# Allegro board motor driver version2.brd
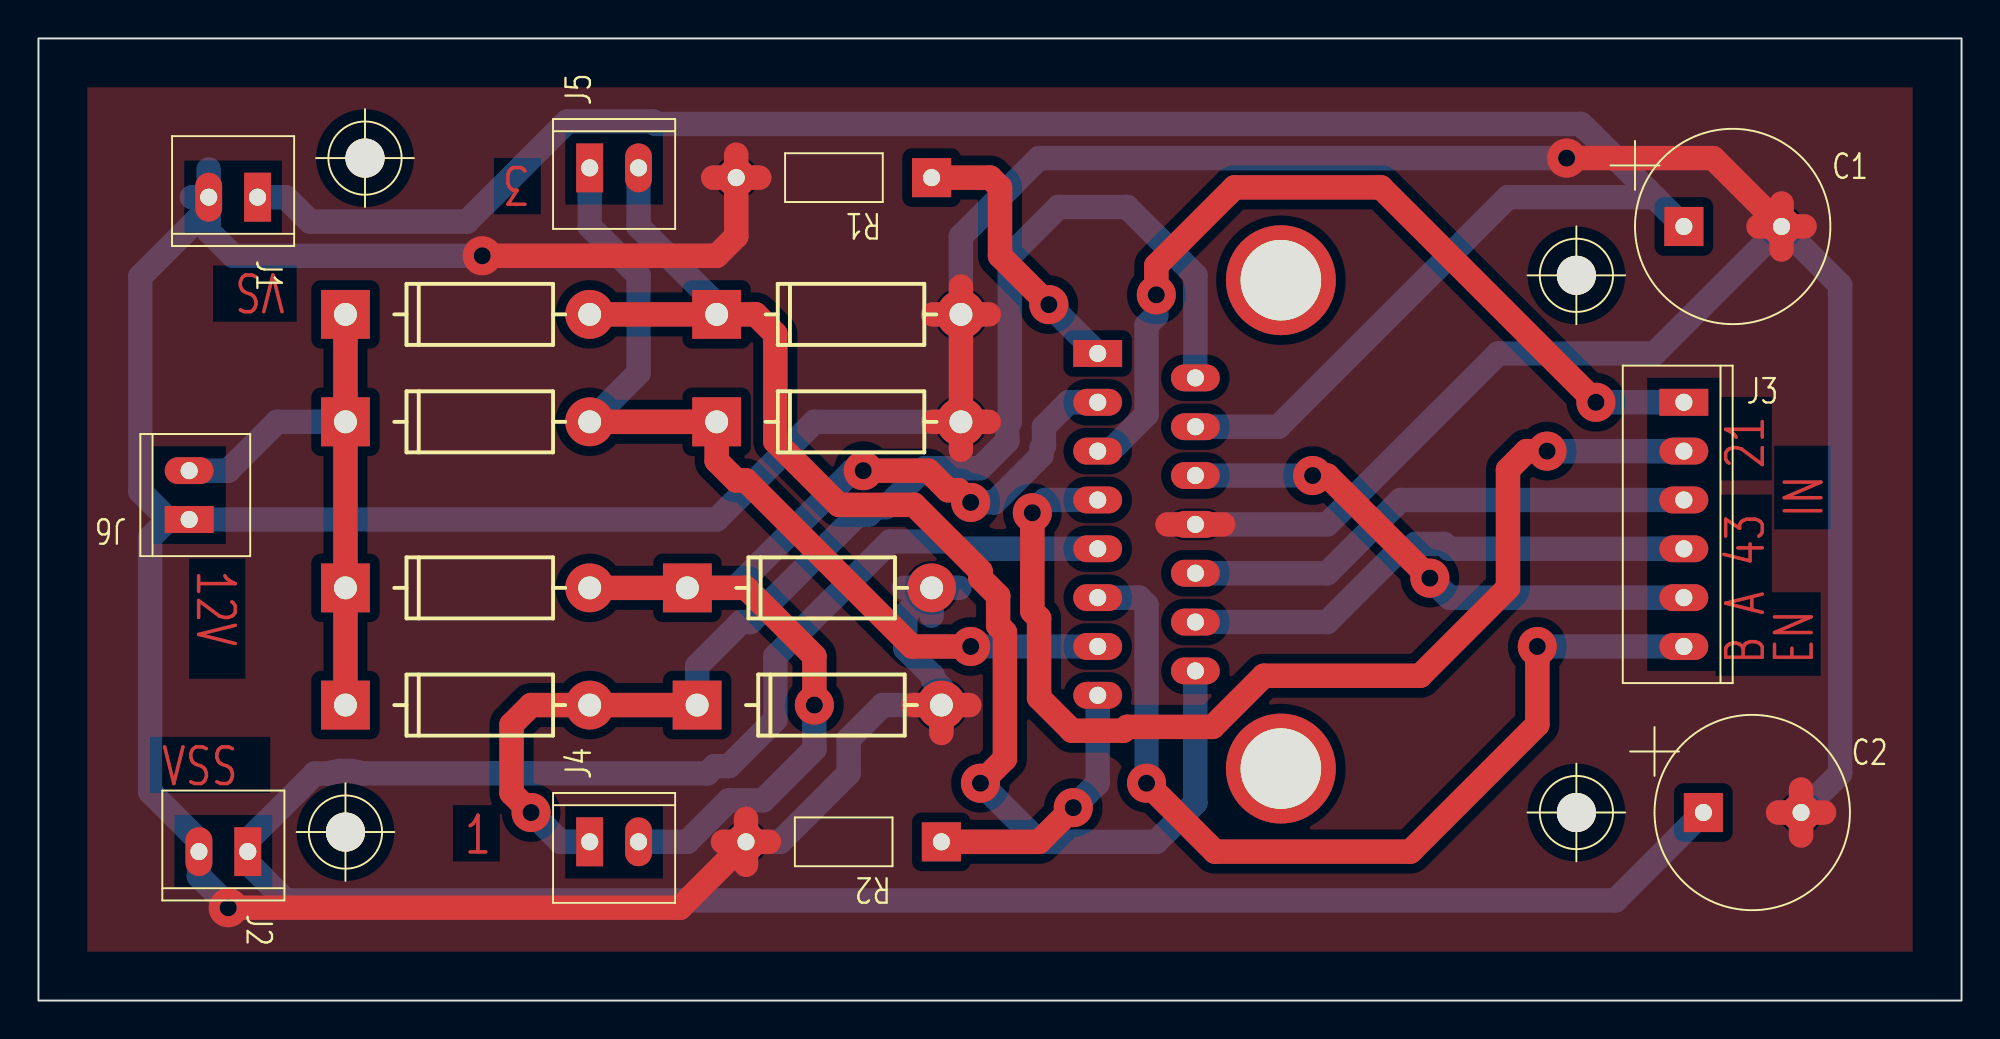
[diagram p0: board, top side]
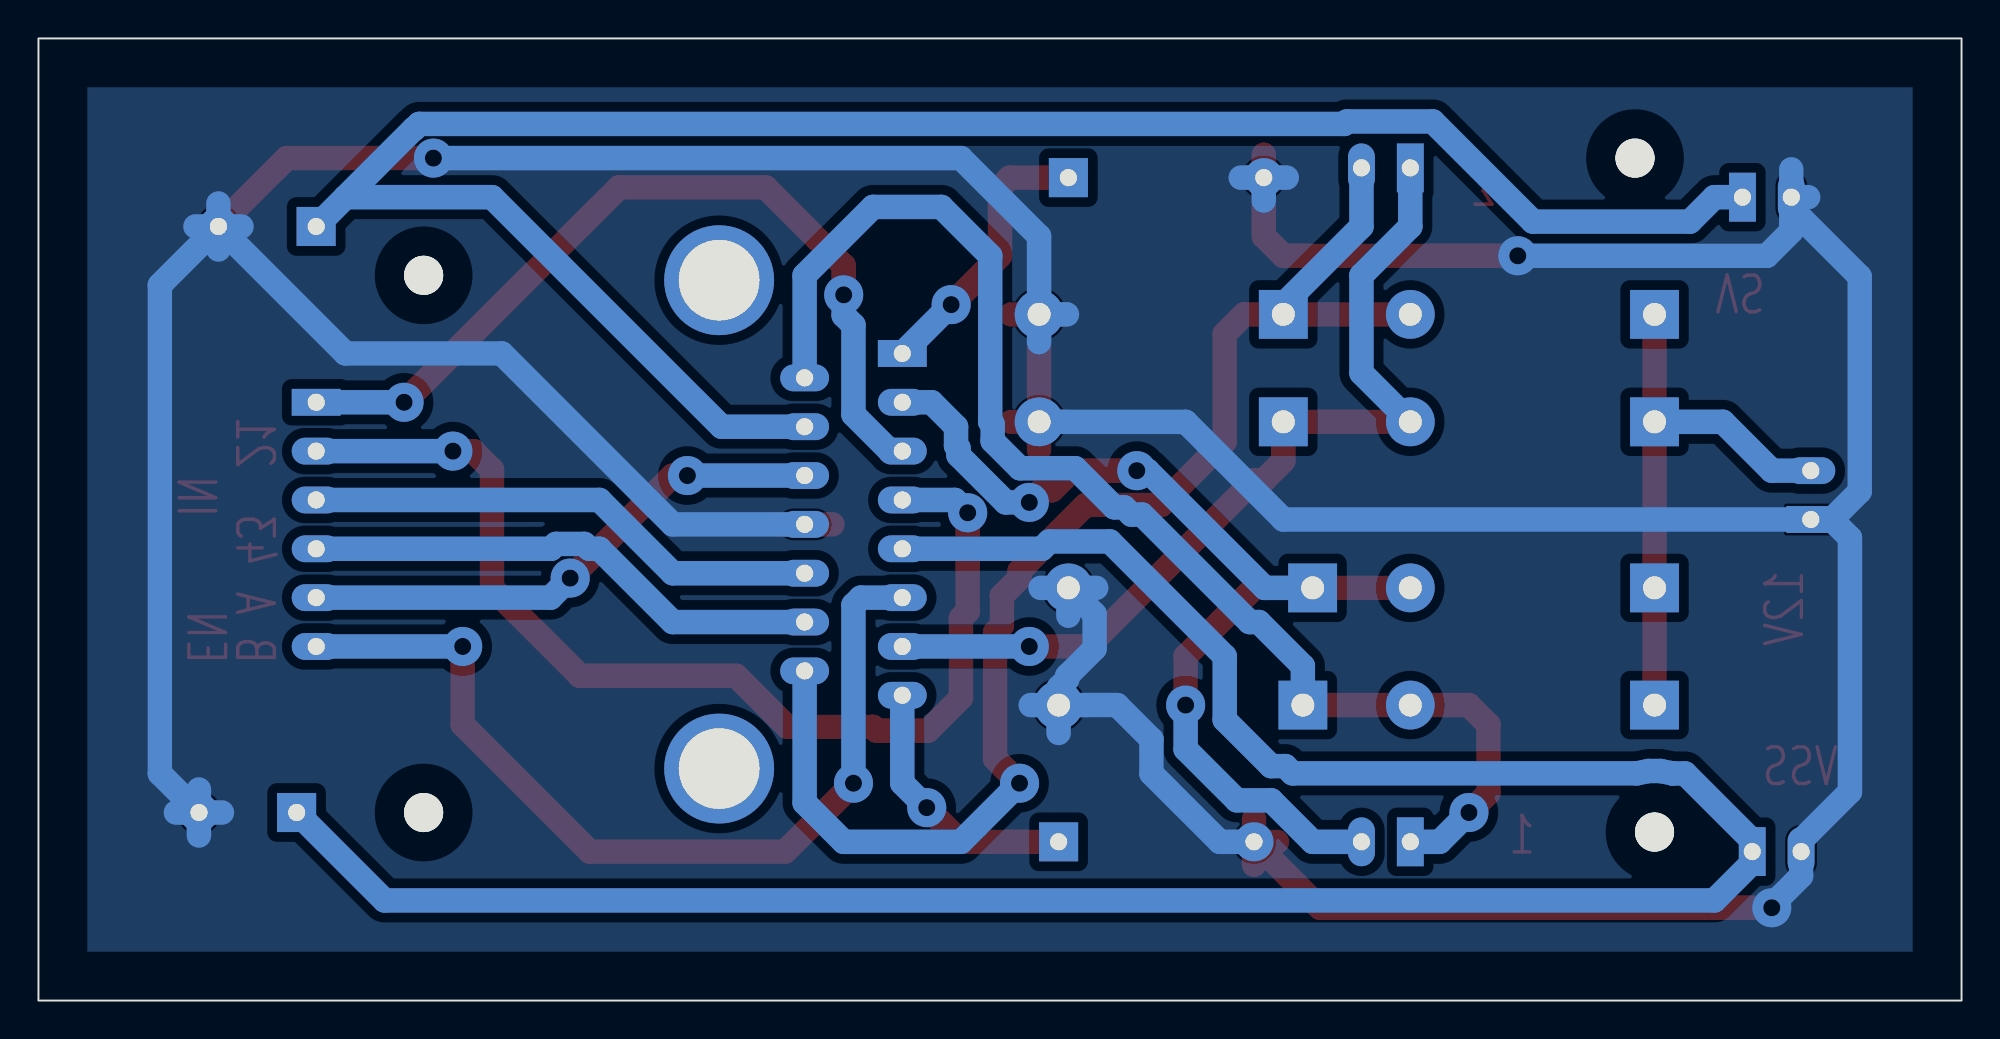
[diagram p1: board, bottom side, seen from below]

Outline 100 x 50.04 mm; copper layers: TOP, BOTTOM. Coordinates in mm from the lower left corner of the outline.
Outline path: rectangle 0,0 100,50.04

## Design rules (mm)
constraint set DEFAULT: min track width 1.27

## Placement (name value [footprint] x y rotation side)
C1  CAP POL  [GU-CAPCYL200]  85.56 40.26 0 top
C2  CAP POL  [GU-CAPCYL200]  86.58 9.78 0 top
D1  DIODE  [GU-1N4001]  34.25 15.37 0 top
D2  DIODE  [GU-1N4001]  15.96 15.37 0 top
D3  DIODE  [GU-1N4001]  33.74 21.46 0 top
D4  DIODE  [GU-1N4001]  15.96 21.46 0 top
D5  DIODE  [GU-1N4001]  35.27 30.1 0 top
D6  DIODE  [GU-1N4001]  15.96 30.1 0 top
D7  DIODE  [GU-1N4001]  35.27 35.69 0 top
D8  DIODE  [GU-1N4001]  15.96 35.69 0 top
J1  CON2  [GU-MOLEX2]  11.39 41.78 270 top
J2  CON2  [GU-MOLEX2]  10.88 7.75 270 top
J3  CON6  [GU-MOLEX6]  85.56 31.11 0 top
J4  CON2  [GU-MOLEX2]  28.66 8.25 90 top
J5  CON2  [GU-MOLEX2]  28.66 43.31 90 top
J6  CON2  [GU-MOLEX2]  7.84 25.02 180 top
NOREF  -  [unnamed]  16.98 43.81 0 top
NOREF#2  -  [unnamed]  79.97 9.78 0 top
NOREF#3  -  [unnamed]  79.97 37.72 90 top
NOREF#4  -  [unnamed]  15.96 8.76 0 top
R1  R  [GU-RC400]  46.44 42.8 180 top
R2  R  [GU-RC400]  46.95 8.25 180 top
U1  L298/MUTIV  [GU-L298-HSINK2]  55.08 33.66 270 top

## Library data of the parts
C1 C2 = CAP POL
D1-D8 = DIODE
J1 J2 J4-J6 = CON2
J3 = CON6
R1 R2 = R
U1 = L298/MUTIV_2

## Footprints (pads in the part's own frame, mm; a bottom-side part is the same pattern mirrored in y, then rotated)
GU-1N4001
  round 2.54 hole 1.194: 1(12.7,0)
  rect 2.54x2.54 hole 1.194: 2(0,0)
GU-CAPCYL200
  rect 2.032x2.032 hole 0.889: 1(0,0)
  round 2.032 hole 0.889: 2(5.08,0)
GU-L298-HSINK2
  round 5.715 hole 4.191 unplated: (-3.81,9.525) (21.59,9.525)
  rect 1.397x2.54 hole 0.889: 1(0,0)
  oval 1.397x2.54 hole 0.889: 2(1.27,5.08) 3(2.54,0) 4(3.81,5.08) 5(5.08,0) 6(6.35,5.08) 7(7.62,0) 8(8.89,5.08) 9(10.16,0) 10(11.43,5.08) 11(12.7,0) 12(13.97,5.08) 13(15.24,0) 14(16.51,5.08) 15(17.78,0)
GU-MOLEX2
  rect 2.54x1.397 hole 0.889: 1(0,0)
  oval 2.54x1.397 hole 0.889: 2(0,-2.54)
GU-MOLEX6
  rect 2.54x1.397 hole 0.889: 1(0,0)
  oval 2.54x1.397 hole 0.889: 2(0,-2.54) 3(0,-5.08) 4(0,-7.62) 5(0,-10.16) 6(0,-12.7)
GU-RC400
  rect 2.032x2.032 hole 0.889: 1(0,0)
  round 2.032 hole 0.889: 2(10.16,0)
unnamed
  round 2.032 hole 3.962 unplated: (0,0)

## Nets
12V: D2.2(CATHODE) D4.2(CATHODE) D6.2(CATHODE) D8.2(CATHODE) J6.2
GND: C1.2 C2.2 D1.1 D3.1 D5.1 D7.1 J1.2 J2.2 J6.1 R1.2 R2.2 U1.8
ENA: J3.5 U1.6
ENB: J3.6 U1.11
IN1: J3.1 U1.5
IN2: J3.2 U1.7
IN3: J3.3 U1.10
IN4: J3.4 U1.12
OUT1: D1.2(CATHODE) D2.1 J4.1 U1.2
OUT2: D3.2(CATHODE) D4.1 J4.2 U1.3
OUT3: D5.2(CATHODE) D6.1 J5.1 U1.13
OUT4: D7.2(CATHODE) D8.1 J5.2 U1.14
N01235: R2.1 U1.15
N01241: R1.1 U1.1
N01245: C1.1 J1.1 U1.4
N01267: C2.1 J2.1 U1.9(VSS)

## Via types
v1: diameter 2.032, hole 0.889, TOP to BOTTOM, 19 vias

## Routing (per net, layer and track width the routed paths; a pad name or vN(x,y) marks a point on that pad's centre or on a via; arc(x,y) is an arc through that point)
12V: length 30
  TOP w1.27: D8.2 D6.2 D4.2 D2.2
  BOTTOM w1.27: 7.33,27.56 J6.2 9.87,27.56 12.41,30.1 D6.2
GND: length 351.4
  TOP w1.27: D1.1 48.4,15.37 ; D1.1 46.95,13.92 ; D1.1 45.5,15.37 ; 46.52,30.1 D5.1 ; D5.1 49.42,30.1 ; D5.1 47.97,28.65 ; D5.1 D7.1 ; 35.6,8.25 R2.2 ; R2.2 36.79,7.06 ; R2.2 37.99,8.25 ; R2.2 36.79,9.45 ; R2.2 33.36,4.83 v1(9.87,4.83) ; 61.61,24.76 U1.8 58.71,24.76 ; C2.2 91.66,10.97 ; C2.2 92.85,9.78 ; C2.2 91.66,8.58 ; C2.2 90.46,9.78 ; R1.2 36.28,39.75 35.27,38.73 v1(23.08,38.73) ; R1.2 35.09,42.8 ; R1.2 36.28,43.99 ; R1.2 37.48,42.8 ; C1.2 90.64,41.45 ; C1.2 87.08,43.81 v1(79.46,43.81) ; C1.2 91.83,40.26 ; C1.2 89.45,40.26 ; C1.2 90.64,39.06 ; D7.1 47.97,37.14 ; D7.1 46.52,35.69 ; D7.1 49.42,35.69
  BOTTOM w1.27: C1.2 84.04,33.66 75.91,33.66 67.02,24.76 U1.8 ; C1.2 90.64,41.45 ; C1.2 91.83,40.26 ; C1.2 90.64,39.06 ; C1.2 93.69,37.21 93.69,11.81 C2.2 ; C1.2 89.45,40.26 ; 91.66,8.58 C2.2 ; C2.2 92.85,9.78 ; C2.2 91.66,10.97 ; C2.2 90.46,9.78 ; 46.95,13.92 D1.1 ; D1.1 46.95,16.27 46.51,16.71 46.51,16.88 45.08,18.3 45.08,20.1 D3.1 ; D1.1 48.4,15.37 ; D1.1 43.9,15.37 42.13,13.59 42.13,11.81 38.57,8.25 R2.2 ; 46.52,35.69 D7.1 ; D7.1 47.97,34.24 ; D7.1 47.97,39.75 52.03,43.81 v1(79.46,43.81) ; 8.85,41.21 5.3,37.66 5.3,26.48 6.76,25.02 ; 8.85,41.21 J1.2 ; 8.85,41.21 8.85,40 10.12,38.73 v1(23.08,38.73) ; 6.76,25.02 J6.1 35.27,25.02 40.35,30.1 D5.1 ; 6.76,25.02 5.8,24.07 5.8,10.86 8.34,8.32 J2.2 8.34,6.48 9.87,4.95 v1(9.87,4.83) ; 45,21.46 D3.1 ; D3.1 47.89,21.46 ; D3.1 46.44,20.01 ; J1.2 8.85,43.23 ; J1.2 7.98,41.78 ; R1.2 37.48,42.8 ; R1.2 36.28,41.6 ; R1.2 35.09,42.8
ENA: length 28
  TOP w1.27: v1(66.26,27.3) 67.02,27.3 v1(72.35,21.97)
  BOTTOM w1.27: U1.6 v1(66.26,27.3) ; J3.5 73.37,20.95 v1(72.35,21.97)
ENB: length 48.2
  TOP w1.27: v1(77.94,18.41) 77.94,14.35 71.34,7.75 61.18,7.75 v1(57.62,11.3)
  BOTTOM w1.27: J3.6 v1(77.94,18.41) ; v1(57.62,11.3) 57.62,20.57 57.24,20.95 U1.11
IN1: length 45
  TOP w1.27: v1(58.13,36.7) 58.13,38.23 62.19,42.29 69.81,42.29 v1(80.99,31.11)
  BOTTOM w1.27: v1(58.13,36.7) 58.13,35.64 57.62,35.13 57.62,30.48 55.72,28.57 U1.5 ; v1(80.99,31.11) J3.1
IN2: length 57.3
  TOP w1.27: v1(51.68,25.37) 51.68,20.24 52.03,19.89 52.03,15.75 53.75,14.03 56.41,14.03 56.61,14.23 61.06,14.23 63.72,16.89 71.84,16.89 76.42,21.46 76.42,27.61 77.38,28.57 v1(78.45,28.57)
  BOTTOM w1.27: U1.7 52.35,26.03 v1(51.68,25.37) ; J3.2 v1(78.45,28.57)
IN3: length 27
  BOTTOM w1.27: J3.3 70.83,26.03 67.02,22.22 U1.10
IN4: length 27.2
  BOTTOM w1.27: U1.12 67.02,19.68 70.83,23.49 71.36,23.49 71.62,23.75 73.09,23.75 73.34,23.49 J3.4
OUT1: length 69
  TOP w1.27: D1.2 D2.1 25.62,15.37 24.6,14.35 24.6,10.79 v1(25.62,9.78)
  BOTTOM w1.27: U1.2 60.16,37.72 56.6,41.27 53.05,41.27 50.51,38.74 50.51,30.1 50.38,29.97 50.38,29.1 48.97,27.69 46.09,27.69 44.06,25.65 43.55,25.65 43.17,25.27 42.61,25.27 37.02,19.68 36.54,19.68 34.25,17.4 D1.2 ; v1(25.62,9.78) 27.14,8.25 J4.1
OUT2: length 56.6
  TOP w1.27: v1(42.89,27.56) 46.28,27.56 47.29,26.54 47.84,26.54 v1(48.48,25.91) ; D4.1 D3.2 36.79,21.46 40.35,17.91 v1(40.35,15.37)
  BOTTOM w1.27: v1(40.35,15.37) 40.35,13.08 37.69,10.41 35.9,10.41 33.74,8.25 J4.2 ; v1(48.48,25.91) 49.7,25.91 52.16,28.36 52.16,28.73 52.29,28.86 52.29,29.84 53.56,31.11 U1.3 ; D3.2 36.23,21.46 42.33,27.56 v1(42.89,27.56)
OUT3: length 47.8
  TOP w1.27: D6.1 D5.2 35.27,28.07 36.28,27.05 36.79,27.05 45.43,18.41 v1(48.48,18.41)
  BOTTOM w1.27: J5.1 28.66,40.26 31.2,37.72 31.2,32.64 D6.1 ; U1.13 v1(48.48,18.41)
OUT4: length 71.4
  TOP w1.27: D8.1 D7.2 37.3,35.69 38.32,34.67 38.32,29.08 41.62,25.78 45.54,25.78 48.98,22.34 48.98,21.97 49.9,21.05 49.9,19.5 50.25,19.15 50.25,12.57 v1(48.98,11.3)
  BOTTOM w1.27: D7.2 35.78,35.69 31.2,40.26 J5.2 ; U1.14 60.16,10.29 58.13,8.25 52.03,8.25 v1(48.98,11.3)
N01235: length 14
  TOP w1.27: R2.1 52.03,8.25 v1(53.81,10.03)
  BOTTOM w1.27: v1(53.81,10.03) 55.08,11.3 U1.15
N01241: length 14.5
  TOP w1.27: v1(52.54,36.2) 50,38.73 50,42.29 49.49,42.8 R1.1
  BOTTOM w1.27: v1(52.54,36.2) U1.1
N01245: length 107.9
  BOTTOM w1.27: C1.1 84.04,41.78 ; 84.04,41.78 80.48,45.34 80.45,45.34 80.2,45.59 32.09,45.59 31.97,45.72 27.49,45.72 22.28,40.51 14.12,40.51 12.85,41.78 J1.1 ; 84.04,41.78 76.42,41.78 64.48,29.84 U1.4
N01267: length 132.3
  BOTTOM w1.27: U1.9 47.82,23.49 47.44,23.88 44.28,23.88 38.32,17.91 38.32,14.61 35.9,12.19 35.16,12.19 34.78,11.82 16.89,11.82 16.28,11.94 15.65,11.94 15.04,11.82 15.03,11.81 14.38,11.81 10.88,8.32 J2.1 10.88,7.18 12.85,5.21 82,5.21 C2.1

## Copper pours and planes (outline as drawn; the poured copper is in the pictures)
GND on TOP: 2.54,47.5 97.46,47.5 97.46,2.54 2.54,2.54 ; 2 cut-outs
GND on BOTTOM: 2.54,47.5 97.46,47.5 97.46,2.54 2.54,2.54 ; 10 cut-outs

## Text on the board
TOP: VSS | 1 | 21 | 43 | A | B | EN | IN | VS | 3 | 12V
